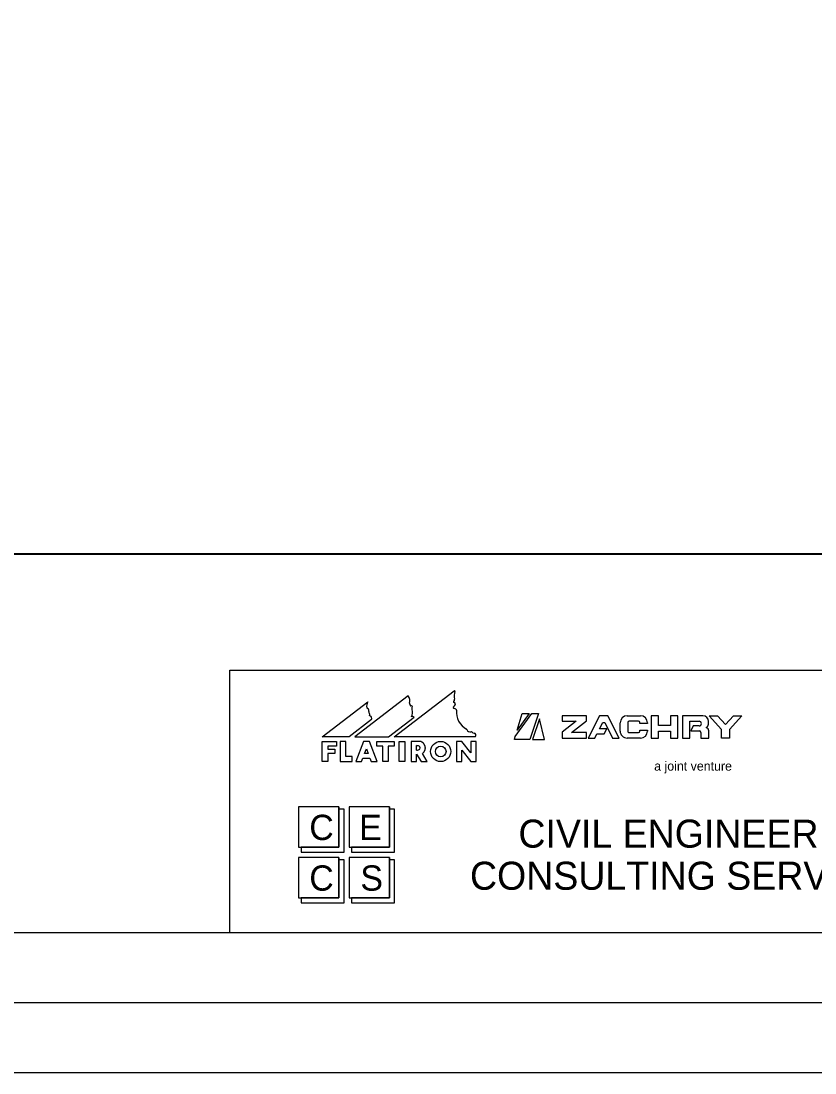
# Model space of a CAD drawing. Extents: x -2251 to 10196, y -13470 to 1199.
# Drawn here: x 3739.3 to 4022.4, y -11950.7 to -11575.7 of the extents above; entities that cross this region are included whole.
import ezdxf

# ---------------------------------------------------------------- set-up
doc = ezdxf.new("R2010")
doc.units = 0
for name, color, linetype in [('Level 3', 7, 'Continuous'), ('RD_SHT_Bndy', 7, 'Continuous'), ('RD_SHT_Iplotshp', 7, 'Continuous'), ('RD_SHT_Logo', 7, 'Continuous'), ('RD_SHT_Misc1', 7, 'Continuous'), ('RD_SHT_Snap', 7, 'Continuous'), ('RD_SHT_TX', 7, 'Continuous'), ('RD_TX_RoadID', 7, 'Continuous')]:
    doc.layers.add(name, color=color, linetype=linetype)

msp = doc.modelspace()

# ---------------------------------------------------------------- linework, layer by layer
at = {"layer": 'Level 3'}
msp.add_line((3965.07, -11863.99), (3965.07, -11863.99), dxfattribs=at)
msp.add_line((3965.07, -11863.99), (3965.07, -11863.99), dxfattribs=at)
msp.add_line((3965.07, -11863.99), (3965.07, -11863.99), dxfattribs=at)
msp.add_line((3965.07, -11863.99), (3965.07, -11863.99), dxfattribs=at)
at = {"layer": 'RD_SHT_Bndy'}
for p, q in [((2603.1, -11900.65), (4278.1, -11900.65)), ((4291.65, -11925.65), (2531.65, -11925.65)), ((4291.6, -11950.7), (2531.6, -11950.65))]:
    msp.add_line(p, q, dxfattribs=at)
msp.add_lwpolyline([(2653.4, -10901.26), (4231.08, -10901.26), (4231.08, -11765.57), (2653.4, -11765.57)], close=True, dxfattribs=at)
at = {"layer": 'RD_SHT_Iplotshp'}
msp.add_lwpolyline([(2496.65, -10825.65), (4296.65, -10825.65), (4296.65, -11925.65), (2496.65, -11925.65)], close=True, dxfattribs=at)
at = {"layer": 'RD_SHT_Logo'}
for p, q in [((3877.35, -11816.27), (3858.31, -11830.86)), ((3872.32, -11830.86), (3893.74, -11814.44)), ((3846.7, -11830.86), (3862.98, -11818.38)), ((3870.3, -11830.86), (3879.48, -11823.82)), ((3915.56, -11830.77), (3921.47, -11822.59)), ((3920.48, -11822.59), (3916.24, -11828.47)), ((3916.24, -11828.47), (3917.96, -11822.59)), ((3917.96, -11822.59), (3920.48, -11822.59)), ((3923.82, -11822.59), (3920.68, -11831.76)), ((3921.47, -11822.59), (3923.82, -11822.59)), ((3940.93, -11823.35), (3932.22, -11823.35)), ((3932.22, -11823.35), (3932.22, -11825.3)), ((3940.93, -11825.16), (3940.93, -11823.35)), ((3945.58, -11823.35), (3941.53, -11831.3)), ((3948.58, -11823.35), (3945.58, -11823.35)), ((3952.63, -11831.3), (3948.58, -11823.35)), ((3955.44, -11823.35), (3960.18, -11823.35)), ((3966.62, -11823.35), (3964.02, -11823.35)), ((3964.02, -11823.35), (3964.02, -11831.3)), ((3966.62, -11826.8), (3966.62, -11823.35)), ((3970.9, -11823.35), (3970.9, -11826.8)), ((3973.51, -11823.35), (3970.9, -11823.35)), ((3973.5, -11831.3), (3973.51, -11823.35)), ((3982.43, -11823.35), (3975.13, -11823.35)), ((3975.13, -11823.35), (3975.13, -11831.3)), ((3984.68, -11823.35), (3987.64, -11823.35)), ((3989.08, -11828.24), (3984.68, -11823.35)), ((3987.64, -11823.35), (3990.48, -11826.51)), ((3990.48, -11826.51), (3993.32, -11823.35)), ((3996.28, -11823.35), (3991.88, -11828.24)), ((3993.32, -11823.35), (3996.28, -11823.35)), ((3864.27, -11824.74), (3856.29, -11830.86)), ((3924.24, -11824.44), (3921.74, -11831.76)), ((3925.99, -11831.76), (3924.24, -11824.44)), ((3937.2, -11825.3), (3932.22, -11829.24)), ((3932.22, -11825.3), (3937.2, -11825.3)), ((3935.63, -11829.35), (3940.93, -11825.16)), ((3945.57, -11827.99), (3946.71, -11825.75)), ((3946.71, -11825.75), (3947.44, -11825.75)), ((3947.44, -11825.75), (3950.27, -11831.3)), ((3952.94, -11828.8), (3952.94, -11825.85)), ((3955.64, -11825.8), (3955.64, -11828.85)), ((3959.48, -11825.3), (3956.14, -11825.3)), ((3959.98, -11826.15), (3959.98, -11825.8)), ((3962.68, -11826.15), (3959.98, -11826.15)), ((3962.68, -11825.85), (3962.68, -11826.15)), ((3970.9, -11826.8), (3966.62, -11826.8)), ((3977.83, -11831.3), (3977.83, -11825.31)), ((3977.83, -11825.31), (3981.07, -11825.31)), ((3979.03, -11826.97), (3978.11, -11828.77)), ((3981.07, -11826.97), (3979.03, -11826.97)), ((3983.68, -11827.6), (3983.68, -11827.47)), ((3984.43, -11826.36), (3984.43, -11825.35)), ((3856.29, -11830.86), (3846.7, -11830.86)), ((3858.31, -11830.86), (3870.3, -11830.86)), ((3901.19, -11830.86), (3872.32, -11830.86)), ((3915.27, -11831.76), (3915.56, -11830.77)), ((3932.22, -11829.24), (3932.22, -11831.3)), ((3932.22, -11831.3), (3940.93, -11831.3)), ((3940.93, -11829.35), (3935.63, -11829.35)), ((3940.93, -11831.3), (3940.93, -11829.35)), ((3941.53, -11831.3), (3943.88, -11831.3)), ((3943.88, -11831.3), (3944.65, -11829.79)), ((3944.65, -11829.79), (3947.23, -11829.79)), ((3948.15, -11827.99), (3945.57, -11827.99)), ((3947.23, -11829.79), (3948.15, -11827.99)), ((3950.27, -11831.3), (3952.63, -11831.3)), ((3960.18, -11831.3), (3955.44, -11831.3)), ((3956.14, -11829.35), (3959.48, -11829.35)), ((3959.98, -11828.5), (3962.68, -11828.5)), ((3959.98, -11828.85), (3959.98, -11828.5)), ((3962.68, -11828.5), (3962.68, -11828.8)), ((3964.02, -11831.3), (3966.62, -11831.3)), ((3966.62, -11831.3), (3966.62, -11828.8)), ((3966.62, -11828.8), (3970.9, -11828.8)), ((3970.9, -11828.8), (3970.9, -11831.3)), ((3970.9, -11831.3), (3973.5, -11831.3)), ((3975.13, -11831.3), (3977.83, -11831.3)), ((3978.11, -11828.77), (3981.24, -11828.77)), ((3981.74, -11829.27), (3981.74, -11831.3)), ((3981.74, -11831.3), (3984.54, -11831.3)), ((3984.54, -11831.3), (3984.54, -11828.76)), ((3989.08, -11831.3), (3989.08, -11828.24)), ((3991.88, -11831.3), (3989.08, -11831.3)), ((3991.88, -11828.24), (3991.88, -11831.3)), ((3846.72, -11839.7), (3846.72, -11832.5)), ((3846.72, -11832.5), (3851.82, -11832.5)), ((3851.82, -11834.15), (3848.67, -11834.15)), ((3848.67, -11834.15), (3848.67, -11835.21)), ((3848.67, -11835.21), (3851.22, -11835.21)), ((3851.22, -11835.21), (3851.22, -11836.86)), ((3851.82, -11832.5), (3851.82, -11834.15)), ((3855.12, -11832.5), (3853.17, -11832.5)), ((3853.17, -11832.5), (3853.17, -11839.7)), ((3855.12, -11837.9), (3855.12, -11832.5)), ((3861.42, -11832.5), (3858.65, -11839.71)), ((3863.52, -11832.5), (3861.42, -11832.5)), ((3861.83, -11836.86), (3862.47, -11835.2)), ((3862.47, -11835.2), (3863.1, -11836.86)), ((3866.28, -11839.71), (3863.52, -11832.5)), ((3866.22, -11834.15), (3866.22, -11832.5)), ((3866.22, -11832.5), (3872.37, -11832.5)), ((3868.32, -11834.15), (3866.22, -11834.15)), ((3868.32, -11839.71), (3868.32, -11834.15)), ((3872.37, -11834.15), (3870.27, -11834.15)), ((3870.27, -11834.15), (3870.27, -11839.71)), ((3872.37, -11832.5), (3872.37, -11834.15)), ((3874.17, -11839.71), (3874.17, -11832.5)), ((3874.17, -11832.5), (3876.12, -11832.5)), ((3876.12, -11832.5), (3876.12, -11839.71)), ((3881.8, -11832.5), (3878.38, -11832.5)), ((3878.38, -11832.5), (3878.38, -11839.71)), ((3880.33, -11835.66), (3880.33, -11834.01)), ((3896.52, -11832.5), (3894.57, -11832.5)), ((3894.57, -11832.5), (3894.57, -11839.71)), ((3899.67, -11836.53), (3896.52, -11832.5)), ((3901.62, -11832.5), (3899.67, -11832.5)), ((3899.67, -11832.5), (3899.67, -11836.53)), ((3901.62, -11839.71), (3901.62, -11832.5)), ((3920.68, -11831.76), (3915.27, -11831.76)), ((3921.74, -11831.76), (3925.99, -11831.76)), ((3851.22, -11836.86), (3848.67, -11836.86)), ((3848.67, -11836.86), (3848.67, -11839.7)), ((3857.37, -11837.9), (3855.12, -11837.9)), ((3857.37, -11839.71), (3857.37, -11837.9)), ((3860.74, -11839.71), (3861.2, -11838.51)), ((3861.2, -11838.51), (3863.74, -11838.51)), ((3863.1, -11836.86), (3861.83, -11836.86)), ((3863.74, -11838.51), (3864.2, -11839.71)), ((3880.33, -11839.71), (3880.33, -11837.02)), ((3880.33, -11837.02), (3881.94, -11839.71)), ((3884.16, -11839.71), (3882.43, -11836.82)), ((3896.52, -11839.71), (3896.52, -11835.67)), ((3896.52, -11835.67), (3899.67, -11839.71)), ((3848.67, -11839.7), (3846.72, -11839.7)), ((3853.17, -11839.7), (3857.37, -11839.71)), ((3858.65, -11839.71), (3860.74, -11839.71)), ((3864.2, -11839.71), (3866.28, -11839.71)), ((3870.27, -11839.71), (3868.32, -11839.71)), ((3876.12, -11839.71), (3874.17, -11839.71)), ((3878.38, -11839.71), (3880.33, -11839.71)), ((3881.94, -11839.71), (3884.16, -11839.71)), ((3894.57, -11839.71), (3896.52, -11839.71)), ((3899.67, -11839.71), (3901.62, -11839.71)), ((3852.67, -11855.79), (3838.28, -11855.79)), ((3838.28, -11855.79), (3838.28, -11870.23)), ((3852.67, -11870.23), (3852.67, -11855.79)), ((3852.67, -11855.79), (3852.67, -11870.23)), ((3854.48, -11856.7), (3852.67, -11856.7)), ((3854.48, -11872.03), (3854.48, -11856.7)), ((3870.67, -11855.79), (3856.27, -11855.79)), ((3856.27, -11855.79), (3856.27, -11870.23)), ((3870.67, -11870.23), (3870.67, -11855.79)), ((3870.67, -11855.79), (3870.67, -11870.23)), ((3872.48, -11856.7), (3870.67, -11856.7)), ((3872.48, -11872.03), (3872.48, -11856.7)), ((3838.28, -11870.23), (3852.67, -11870.23)), ((3852.67, -11870.23), (3839.17, -11870.23)), ((3839.17, -11870.23), (3839.17, -11872.03)), ((3839.17, -11872.03), (3854.48, -11872.03)), ((3856.27, -11870.23), (3870.67, -11870.23)), ((3870.67, -11870.23), (3857.18, -11870.23)), ((3857.18, -11870.23), (3857.18, -11872.03)), ((3857.18, -11872.03), (3872.48, -11872.03)), ((3852.67, -11873.84), (3838.28, -11873.84)), ((3838.28, -11873.84), (3838.28, -11888.27)), ((3852.67, -11888.27), (3852.67, -11873.84)), ((3852.67, -11873.84), (3852.67, -11888.27)), ((3854.48, -11874.74), (3852.67, -11874.74)), ((3854.48, -11890.07), (3854.48, -11874.74)), ((3870.67, -11873.84), (3856.27, -11873.84)), ((3856.27, -11873.84), (3856.27, -11888.27)), ((3870.67, -11888.27), (3870.67, -11873.84)), ((3870.67, -11873.84), (3870.67, -11888.27)), ((3872.48, -11874.74), (3870.67, -11874.74)), ((3872.48, -11890.07), (3872.48, -11874.74)), ((3838.28, -11888.27), (3852.67, -11888.27)), ((3852.67, -11888.27), (3839.17, -11888.27)), ((3839.17, -11888.27), (3839.17, -11890.07)), ((3839.17, -11890.07), (3854.48, -11890.07)), ((3856.27, -11888.27), (3870.67, -11888.27)), ((3870.67, -11888.27), (3857.18, -11888.27)), ((3857.18, -11888.27), (3857.18, -11890.07)), ((3857.18, -11890.07), (3872.48, -11890.07))]:
    msp.add_line(p, q, dxfattribs=at)
for radius in [3.6, 1.9]:
    msp.add_circle((3888.95, -11836.1), radius, dxfattribs=at)
for centre, radius, start, end in [((3875.05, -11818.02), 2.89, 342.0343, 37.2653), ((3897.87, -11816.34), 4.17, 156.4699, 195.3053), ((3893.86, -11814.6), 0.2, 336.4699, 127.4657), ((3866.29, -11820.12), 3.74, 152.2252, 185.8662), ((3877.99, -11818.97), 0.2, 162.0343, 220.8638), ((3876.86, -11819.95), 1.3, 11.8745, 40.8638), ((3878.32, -11819.64), 0.2, 191.8745, 279.8173), ((3878.44, -11820.33), 0.499, 44.4799, 99.8173), ((3879.5, -11820.72), 0.843, 144.641, 212.5499), ((3878.65, -11820.12), 0.2, 324.641, 44.4799), ((3893.57, -11820.5), 0.2, 133.0036, 262.3069), ((3891.59, -11818.37), 2.7, 313.0036, 343.6807), ((3893.73, -11818.39), 0.2, 129.4079, 246.863), ((3893.13, -11817.66), 0.749, 309.4079, 17.0499), ((3893.27, -11819.47), 0.973, 20.4113, 66.863), ((3862.1, -11821.62), 1.21, 351.6466, 67.1294), ((3864.29, -11821.94), 1, 171.6466, 221.9371), ((3863.11, -11823.01), 0.592, 327.6019, 41.9371), ((3863.3, -11824.33), 1.05, 337.4201, 73.1261), ((3875.8, -11822.18), 3.16, 331.2486, 18.4584), ((3878.92, -11824.44), 0.827, 48.0701, 115.7229), ((3893.31, -11822.44), 1.76, 45.283, 82.3069), ((3894.4, -11821.33), 0.2, 353.8329, 45.283), ((3901.36, -11822.08), 6.8, 173.8329, 242.3928), ((3955.44, -11825.85), 2.5, 89.9984, 179.9984), ((3960.18, -11825.85), 2.5, 359.9984, 89.9984), ((3982.43, -11825.35), 2, 359.9984, 89.9984), ((3956.14, -11825.8), 0.5, 89.9984, 179.9984), ((3959.48, -11825.8), 0.5, 359.9984, 89.9984), ((3981.07, -11826.14), 0.831, 269.9984, 89.9984), ((3983.23, -11826.36), 1.2, 291.95, 359.9984), ((3983.34, -11828.76), 1.2, 359.9984, 73.7977), ((3898.12, -11828.28), 0.2, 9.0833, 62.3928), ((3899.35, -11828.09), 1.04, 189.0833, 295.769), ((3899.89, -11829.21), 0.2, 33.7112, 115.769), ((3900.89, -11828.54), 1.01, 213.7112, 268.6299), ((3900.86, -11829.74), 0.2, 78.9712, 88.6299), ((3900.75, -11830.3), 0.767, 320.912, 78.9712), ((3901.19, -11830.66), 0.2, 269.9984, 320.912), ((3955.44, -11828.8), 2.5, 179.9984, 269.9984), ((3956.14, -11828.85), 0.5, 179.9984, 269.9984), ((3959.48, -11828.85), 0.5, 269.9984, 359.9984), ((3960.18, -11828.8), 2.5, 269.9984, 359.9984), ((3981.24, -11829.27), 0.5, 359.9984, 89.9984)]:
    msp.add_arc(centre, radius, start, end, dxfattribs=at)
msp.add_ellipse((3880.33, -11834.83), major_axis=(1.36, 0), ratio=0.609965, start_param=4.712389, end_param=7.853982, dxfattribs=at)
msp.add_open_spline([(3882.43, -11836.82), (3882.51, -11836.76), (3882.59, -11836.7), (3882.81, -11836.49), (3882.95, -11836.34), (3883.13, -11836.07), (3883.19, -11835.97), (3883.29, -11835.77), (3883.34, -11835.66), (3883.41, -11835.44), (3883.44, -11835.32), (3883.47, -11835.08), (3883.48, -11834.96), (3883.48, -11834.71), (3883.47, -11834.59), (3883.44, -11834.35), (3883.41, -11834.23), (3883.34, -11834.01), (3883.29, -11833.9), (3883.19, -11833.7), (3883.13, -11833.6), (3882.95, -11833.33), (3882.81, -11833.18), (3882.52, -11832.91), (3882.37, -11832.8), (3882.08, -11832.63), (3881.94, -11832.56), (3881.8, -11832.5)], degree=3, dxfattribs=at)
at = {"layer": 'RD_SHT_Misc1'}
msp.add_lwpolyline([(4296.65, -11925.65), (4296.68, -10825.65), (2596.68, -10825.6), (2596.65, -11925.6)], close=True, dxfattribs=at)
at = {"layer": 'RD_SHT_Snap'}
msp.add_lwpolyline([(2508.15, -10825.65), (4308.15, -10825.65), (4308.15, -11925.65), (2508.15, -11925.65)], close=True, dxfattribs=at)
at = {"layer": 'RD_SHT_TX'}
for p, q in [((3813.76, -11900.65), (3813.76, -11807.15)), ((3813.76, -11900.65), (3813.76, -11807.15)), ((3813.76, -11807.15), (4278.1, -11807.15))]:
    msp.add_line(p, q, dxfattribs=at)
at = {"layer": 'RD_TX_RoadID'}
msp.add_lwpolyline([(2650.54, -11765.73), (4233.93, -11765.73), (4233.93, -10962.61), (2650.54, -10962.61)], close=True, dxfattribs=at)

# ---------------------------------------------------------------- texts
at = {"layer": 'RD_SHT_Logo'}
msp.add_text('a joint venture', height=3.3, rotation=359.9984, dxfattribs=at).set_placement((3965.08, -11842.93))
for s, height, p in [('C', 9.02, (3842.11, -11867.66)), ('E', 9.02, (3859.9, -11867.66)), ('CIVIL ENGINEERING', 10, (3916.67, -11870.38)), ('C', 9.02, (3842.11, -11885.71)), ('S', 9.02, (3860.32, -11885.71)), ('CONSULTING SERVICES, INC.', 10, (3899.39, -11885.38))]:
    msp.add_text(s, height=height, dxfattribs=at).set_placement(p)

doc.saveas('drawing.dxf')
